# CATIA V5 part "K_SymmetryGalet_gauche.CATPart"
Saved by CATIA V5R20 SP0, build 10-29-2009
Part number: Symmetry of Galet_gauche
Bounding box of the stored display mesh (mm): x 0 to 17.955, y -11.571 to 11.571, z -11.571 to 11.571
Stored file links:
  G:\Khaled_CFAO_2011\SIL\SIL_GR2\zthiebault\Khaled\CAD_ThinkMOTION\K_SymmetryGalet_gauche.CATPart
  G:\Khaled_CFAO_2011\SIL\SIL_GR2\zthiebault\Khaled\CAD_ThinkMOTION\K_Galet_gauche.CATPart
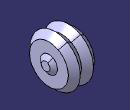
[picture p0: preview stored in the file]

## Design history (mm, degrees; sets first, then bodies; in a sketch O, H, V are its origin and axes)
Body1 (main body)
  Body2 "Corps du corps principal d'origine"
    Solid1: linked copy from another document
  Assemble1: tool Body2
